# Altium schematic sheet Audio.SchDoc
size A4; Organization: Altium Limited; Address1: L3, 12a Rodborough Rd; Address2: Frenchs Forest; Address3: NSW; Address4: Australia 2086
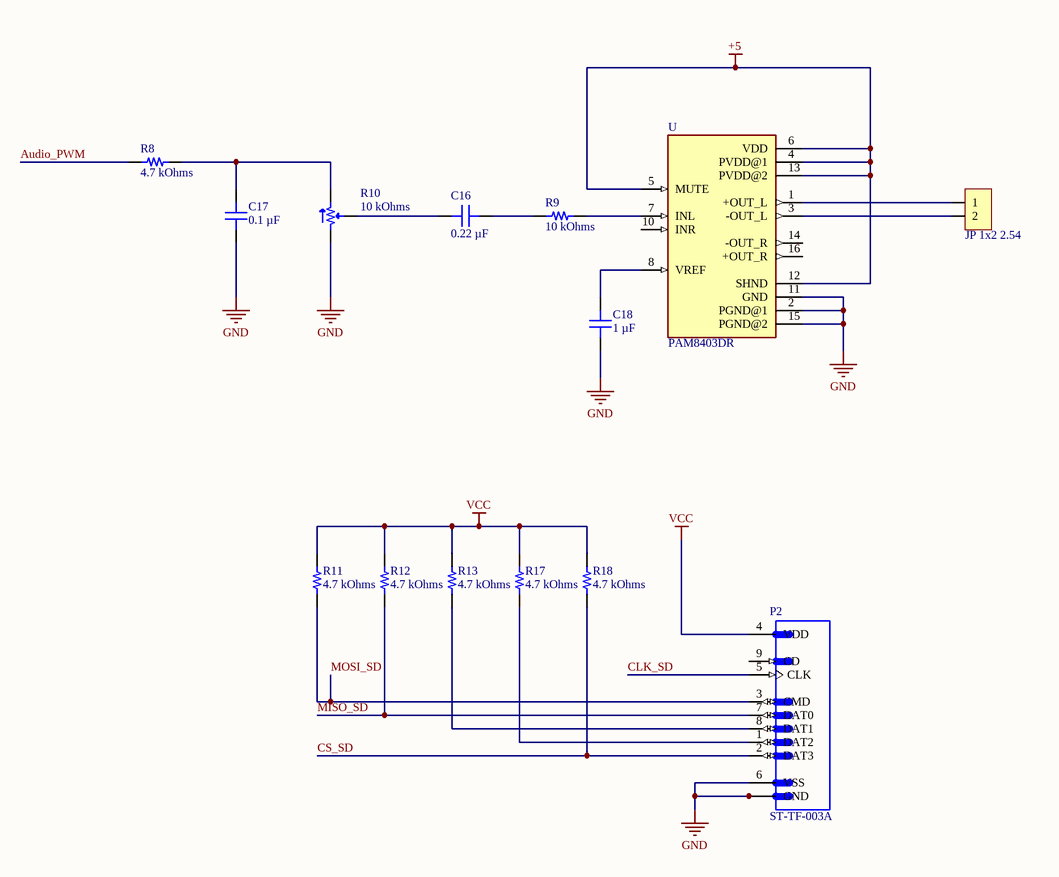
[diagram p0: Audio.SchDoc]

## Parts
C16  0.22 µF  [CAP 0402_1005]
C17  0.1 µF  [CAP 0402_1005]
C18  1 µF  [CAP 0402_1005]
JP5  JP 1x2 2.54  [JP 1x2 CT]
P2  ST-TF-003A  [SUNTECH_ST-TF-003A]
R8  4.7 kOhms  [RES 0402_1005]
R9  10 kOhms  [RES 0402_1005]
R10  10 kOhms  [BOURNS TRIMPOT 3362P-1]
R11  4.7 kOhms  [RES 0402_1005]
R12  4.7 kOhms  [RES 0402_1005]
R13  4.7 kOhms  [RES 0402_1005]
R17  4.7 kOhms  [RES 0402_1005]
R18  4.7 kOhms  [RES 0402_1005]
U  PAM8403DR  [SOIC127P605X150-16N]

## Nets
+5: U.4(PVDD@1) U.5(MUTE) U.6(VDD) U.12(SHND) U.13(PVDD@2)
GND: C17.1 C18.1 P2.6(VSS) P2.G1(GND) P2.G2(GND) P2.G3(GND) P2.G4(GND) R10.1 U.2(PGND@1) U.11(GND) U.15(PGND@2)
VCC: P2.4(VDD) R11.2 R12.2 R13.2 R17.2 R18.2
Audio_PWM: R8.2
CLK_SD: P2.5(CLK)
CS_SD: P2.2(DAT3) R18.1
MISO_SD: P2.7(DAT0) R12.1
MOSI_SD: P2.3(CMD) R11.1
NetC16_1: C16.1 R10.2
NetC16_2: C16.2 R9.1
NetC17_2: C17.2 R8.1 R10.3
NetC18_2: C18.2 U.8(VREF)
NetJP5_1: JP5.1 U.1(+OUT_L)
NetJP5_2: JP5.2 U.3(-OUT_L)
NetP2_1: P2.1(DAT2) R17.1
NetP2_8: P2.8(DAT1) R13.1
NetR9_2: R9.2 U.7(INL)

Not connected (* = marked no-connect by the designer): P2 9(CD); U 10(INR) 14(-OUT_R) 16(+OUT_R)

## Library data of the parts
C16 = 0402X224K100CT: CAP CER 0.22UF 10V X5R 0402; manufacturer: Walsin Technology Corporation; Tolerance: ±10%
C17 = CGA2B2X5R1A104M050BA: CAP CER 0.1UF 10V X5R 0402; manufacturer: TDK Corporation; Tolerance: ±20%
C18 = C0402C105K8PAC7867: CAP CER 1UF 10V X5R 0402; manufacturer: KEMET; Tolerance: ±10%
JP5 = JP 1x2 2.54 Cai Thang: Cắm; Ten_Linh_Kien: Jump Đơn Cái 2.54MM 1x20P Thẳng; Don_Vi: Con; Ma_Hang: MH004006
P2 = ST-TF-003A: Micro SD Card Socket
R8 R11-R13 R17 R18 = RK73H1ERTTP4701F: RES 4.7K OHM 1% 1/10W 0402; Manufacturer: KOA Speer Electronics, Inc.; Power (Watts): 0.1W, 1/10W; Temperature Coefficient: ±100ppm/°C
R9 = MCS0402MC1002FE000: RES SMD 10K OHM 1% 1/10W 0402; Manufacturer: Vishay Beyschlag; Power (Watts): 0.1W, 1/10W; Temperature Coefficient: ±50ppm/°C
R10 = 3362P-1-103LF: TRIMMER 10K OHM 0.5W PC PIN TOP; Manufacturer: Bourns Inc.; Adjustment Type: Top Adjustment; Number of Turns: 1; Power (Watts): 0.5W, 1/2W; Resistive Material: Cermet; Temperature Coefficient: ±100ppm/°C; Tolerance: ±10%
U = PAM8403DR: Amplifier IC 2-Channel _Stereo_ Class D 16-SOP; MF: Diodes Inc.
